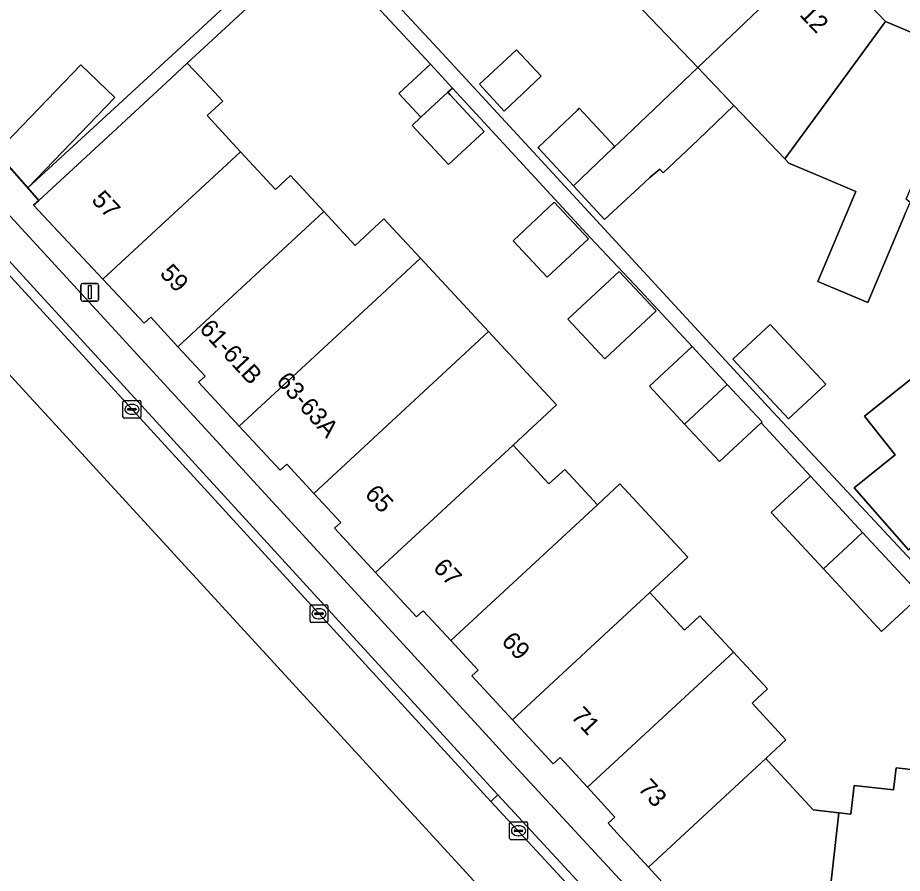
# Model space of a CAD drawing. Extents: x 160663 to 161506, y 382245 to 383291.
# Drawn here: x 160804.12 to 160853.7, y 382955.67 to 383003.62 of the extents above; entities that cross this region are included whole.
import ezdxf

# ---------------------------------------------------------------- set-up
doc = ezdxf.new("R2010")
doc.units = 0
for name, color, linetype in [('IMGEO_Berm_gesloten', 7, 'Continuous'), ('IMGEO_Berm_open', 7, 'Continuous'), ('IMGEO_Erf', 7, 'Continuous'), ('IMGEO_Fietspad_gesloten', 7, 'Continuous'), ('IMGEO_Hek', 7, 'Continuous'), ('IMGEO_Kolk', 7, 'Continuous'), ('IMGEO_Lichtmast', 7, 'Continuous'), ('IMGEO_Pand', 7, 'Continuous'), ('IMGEO_Pand_nummerreeks', 7, 'Continuous'), ('IMGEO_Rijbaan_lokaal_gesloten', 7, 'Continuous'), ('IMGEO_Voetpad_open', 7, 'Continuous')]:
    doc.layers.add(name, color=color, linetype=linetype)

msp = doc.modelspace()

# ---------------------------------------------------------------- linework, layer by layer
at = {"layer": 'IMGEO_Berm_gesloten'}
msp.add_lwpolyline([(160840.811, 382949.506), (160831.032, 382960.06), (160830.64, 382959.7), (160842.06, 382947.363), (160845.035, 382944.34)], dxfattribs=at)
at = {"layer": 'IMGEO_Berm_open'}
msp.add_lwpolyline([(160777.628, 383018.442), (160777.232, 383018.081), (160830.64, 382959.7), (160831.032, 382960.06), (160829.19, 382962.074)], close=True, dxfattribs=at)
at = {"layer": 'IMGEO_Erf'}
for points in [[(160820.979, 383009.117), (160827.916, 383001.628), (160836.559, 382992.249), (160846.446, 382981.528), (160856.563, 382970.677)], [(160803.219, 383006.978), (160797.729, 383001.848), (160802.734, 382996.483), (160803.356, 382997.063), (160803.561, 382996.843), (160802.837, 382996.169), (160802.928, 382996.067), (160802.964, 382996.104), (160807.668, 383000.985), (160809.572, 382999.15), (160804.689, 382994.083), (160813.018, 383001.742), (160820.162, 383008.359)], [(160854.741, 382971.255), (160852.536, 382969.213), (160849.276, 382972.733), (160846.36, 382975.881), (160848.565, 382977.923), (160845.786, 382980.915), (160843.448, 382978.744), (160841.495, 382980.848), (160839.527, 382982.967), (160841.924, 382985.193), (160839.009, 382988.326), (160836.207, 382991.309), (160828.491, 382999.682), (160828.231, 382999.442), (160828.361, 382999.302), (160830.27, 382997.244), (160828.268, 382995.387), (160826.227, 382997.587), (160826.726, 382998.048), (160825.491, 382999.382), (160827.256, 383001.016), (160820.93, 383007.845)], [(160820.773, 383007.699), (160813.63, 383001.082), (160814.643, 383000), (160815.625, 382998.952), (160814.739, 382998.133), (160816.611, 382996.109), (160818.57, 382993.991), (160819.413, 382994.771), (160821.274, 382992.758), (160823.029, 382990.861), (160824.645, 382992.359), (160826.701, 382990.141), (160830.511, 382986.03), (160834.318, 382981.922), (160831.885, 382979.668), (160833.899, 382977.491), (160834.78, 382978.304), (160836.612, 382976.322), (160837.878, 382977.495), (160841.69, 382973.381), (160839.553, 382971.401), (160841.496, 382969.3), (160842.359, 382970.098), (160844.239, 382968.065), (160846.148, 382966), (160845.279, 382965.197), (160847.178, 382963.143), (160846.051, 382962.099), (160846.203, 382961.935), (160848.711, 382959.223), (160850.148, 382959.057), (160850.826, 382958.978), (160851.013, 382960.595), (160853.215, 382960.341), (160853.358, 382961.58), (160856.012, 382961.273)], [(160853.869, 382992.624), (160851.769, 382987.659), (160848.972, 382988.842), (160851.103, 382993.881), (160849.256, 382994.662), (160847.348, 382995.469), (160847.11, 382995.719), (160844.266, 382998.703), (160842.253, 382996.786), (160840.301, 382994.927), (160840.106, 382995.137), (160839.566, 382994.683), (160839.211, 382994.353), (160837.02, 382992.322), (160835.278, 382994.2), (160833.332, 382996.298), (160833.286, 382996.348), (160835.493, 382998.45), (160835.601, 382998.553), (160837.594, 382996.405), (160837.793, 382996.595), (160842.238, 383000.83), (160838.295, 383004.966)]]:
    msp.add_lwpolyline(points, dxfattribs=at)
for points in [[(160831.395, 382998.386), (160829.998, 382999.892), (160832.087, 383001.83), (160833.457, 383000.353)], [(160858.301, 382972.903), (160856.2, 382975.524), (160854.056, 382973.806), (160851.005, 382977.28), (160853.31, 382979.129), (160851.584, 382981.282), (160868.693, 382994.955), (160869.499, 382993.947), (160871.428, 382995.489), (160870.623, 382996.497), (160872.873, 382998.295), (160873.684, 382997.28), (160874.675, 382985.916), (160870.465, 382991.167), (160864.317, 382986.237), (160868.471, 382981.057)], [(160833.802, 382989.08), (160831.888, 382991.119), (160834.187, 382993.277), (160836.115, 382991.224)], [(160839.899, 382987.195), (160837.034, 382984.505), (160834.955, 382986.718), (160837.838, 382989.39)], [(160849.411, 382983.079), (160847.324, 382981.141), (160844.213, 382984.491), (160846.3, 382986.429)]]:
    msp.add_lwpolyline(points, close=True, dxfattribs=at)
at = {"layer": 'IMGEO_Fietspad_gesloten'}
msp.add_lwpolyline([(160842.206, 382950.625), (160831.457, 382962.256), (160830.559, 382963.235), (160777.267, 383021.287), (160777.628, 383018.442), (160829.19, 382962.074), (160831.032, 382960.06), (160840.811, 382949.506)], dxfattribs=at)
at = {"layer": 'IMGEO_Hek'}
msp.add_lwpolyline([(160805.311, 382993.382), (160802.837, 382996.169)], dxfattribs=at)
at = {"layer": 'IMGEO_Kolk'}
for p, q in [((160810.026, 382981.246), (160810.026, 382982.098)), ((160810.101, 382982.172), (160810.953, 382982.172)), ((160811.027, 382982.098), (160811.027, 382981.246)), ((160810.285, 382981.666), (160810.285, 382981.678)), ((160810.723, 382981.629), (160810.325, 382981.629)), ((160810.328, 382981.715), (160810.726, 382981.715)), ((160810.514, 382981.952), (160810.539, 382981.952)), ((160810.769, 382981.678), (160810.769, 382981.666)), ((160810.953, 382981.172), (160810.101, 382981.172)), ((160810.537, 382981.392), (160810.512, 382981.392)), ((160820.511, 382969.791), (160820.511, 382970.643)), ((160820.586, 382970.717), (160821.438, 382970.717)), ((160821.512, 382970.643), (160821.512, 382969.791)), ((160820.77, 382970.211), (160820.77, 382970.223)), ((160821.208, 382970.174), (160820.81, 382970.174)), ((160820.813, 382970.26), (160821.211, 382970.26)), ((160820.999, 382970.497), (160821.024, 382970.497)), ((160821.254, 382970.223), (160821.254, 382970.211)), ((160821.438, 382969.717), (160820.586, 382969.717)), ((160821.022, 382969.937), (160820.997, 382969.937)), ((160831.693, 382957.624), (160831.693, 382958.476)), ((160831.768, 382958.55), (160832.62, 382958.55)), ((160832.181, 382958.33), (160832.206, 382958.33)), ((160832.694, 382958.476), (160832.694, 382957.624)), ((160831.952, 382958.044), (160831.952, 382958.056)), ((160832.39, 382958.007), (160831.992, 382958.007)), ((160831.995, 382958.093), (160832.393, 382958.093)), ((160832.204, 382957.77), (160832.179, 382957.77)), ((160832.436, 382958.056), (160832.436, 382958.044)), ((160832.62, 382957.55), (160831.768, 382957.55))]:
    msp.add_line(p, q, dxfattribs=at)
for points in [[(160810.026, 382981.246), (160810.026, 382982.098)], [(160810.101, 382982.172), (160810.953, 382982.172)], [(160811.027, 382982.098), (160811.027, 382981.246)], [(160810.953, 382981.172), (160810.101, 382981.172)], [(160820.511, 382969.791), (160820.511, 382970.643)], [(160820.586, 382970.717), (160821.438, 382970.717)], [(160821.512, 382970.643), (160821.512, 382969.791)], [(160821.438, 382969.717), (160820.586, 382969.717)], [(160831.693, 382957.624), (160831.693, 382958.476)], [(160831.768, 382958.55), (160832.62, 382958.55)], [(160832.694, 382958.476), (160832.694, 382957.624)], [(160832.62, 382957.55), (160831.768, 382957.55)]]:
    msp.add_lwpolyline(points, dxfattribs=at)
for centre, radius, start, end in [((160810.103, 382982.096), 0.0765, 91.552, 178.448), ((160810.103, 382982.096), 0.0765, 91.552, 178.448), ((160810.951, 382982.096), 0.0765, 1.552, 88.448), ((160810.951, 382982.096), 0.0765, 1.552, 88.448), ((160810.325, 382981.675), 0.0403, 85.8775, 175.7526), ((160810.322, 382981.665), 0.0366, 178.938, 274.7102), ((160810.726, 382981.672), 0.043, 264.8664, 352.4533), ((160810.73, 382981.677), 0.0386, 1.7309, 96.639), ((160810.103, 382981.248), 0.0765, 181.552, 268.448), ((160810.103, 382981.248), 0.0765, 181.552, 268.448), ((160810.951, 382981.248), 0.0765, 271.552, 358.448), ((160810.951, 382981.248), 0.0765, 271.552, 358.448), ((160820.588, 382970.641), 0.0765, 91.552, 178.448), ((160820.588, 382970.641), 0.0765, 91.552, 178.448), ((160821.436, 382970.641), 0.0765, 1.552, 88.448), ((160821.436, 382970.641), 0.0765, 1.552, 88.448), ((160820.81, 382970.22), 0.0403, 85.8775, 175.7526), ((160820.807, 382970.21), 0.0366, 178.938, 274.7102), ((160821.211, 382970.217), 0.043, 264.8664, 352.4533), ((160821.215, 382970.222), 0.0386, 1.7309, 96.639), ((160820.588, 382969.793), 0.0765, 181.552, 268.448), ((160820.588, 382969.793), 0.0765, 181.552, 268.448), ((160821.436, 382969.793), 0.0765, 271.552, 358.448), ((160821.436, 382969.793), 0.0765, 271.552, 358.448), ((160831.77, 382958.474), 0.0765, 91.552, 178.448), ((160831.77, 382958.474), 0.0765, 91.552, 178.448), ((160832.618, 382958.474), 0.0765, 1.552, 88.448), ((160832.618, 382958.474), 0.0765, 1.552, 88.448), ((160831.992, 382958.053), 0.0403, 85.8775, 175.7526), ((160831.989, 382958.043), 0.0366, 178.938, 274.7102), ((160832.393, 382958.05), 0.043, 264.8664, 352.4533), ((160832.397, 382958.055), 0.0386, 1.7309, 96.639), ((160831.77, 382957.626), 0.0765, 181.552, 268.448), ((160831.77, 382957.626), 0.0765, 181.552, 268.448), ((160832.618, 382957.626), 0.0765, 271.552, 358.448), ((160832.618, 382957.626), 0.0765, 271.552, 358.448)]:
    msp.add_arc(centre, radius, start, end, dxfattribs=at)
for centre, major_axis, ratio, start_param, end_param in [((160810.513, 382981.672), (-0.387, 0.002), 0.722429, 4.712389, 7.853982), ((160810.538, 382981.672), (-0.39, 0.002), 0.717154, 1.570796, 4.712389), ((160820.998, 382970.217), (-0.387, 0.002), 0.722429, 4.712389, 7.853982), ((160821.023, 382970.217), (-0.39, 0.002), 0.717154, 1.570796, 4.712389), ((160832.18, 382958.05), (-0.387, 0.002), 0.722429, 4.712389, 7.853982), ((160832.205, 382958.05), (-0.39, 0.002), 0.717154, 1.570796, 4.712389)]:
    msp.add_ellipse(centre, major_axis=major_axis, ratio=ratio, start_param=start_param, end_param=end_param, dxfattribs=at)
at = {"layer": 'IMGEO_Lichtmast'}
for p, q in [((160807.668, 382987.833), (160807.668, 382988.633)), ((160807.668, 382988.633), (160807.668, 382987.833)), ((160807.768, 382988.733), (160808.558, 382988.733)), ((160808.558, 382988.733), (160807.768, 382988.733)), ((160808.658, 382988.633), (160808.658, 382987.833)), ((160808.658, 382987.833), (160808.658, 382988.633)), ((160808.558, 382987.733), (160807.768, 382987.733)), ((160807.768, 382987.733), (160808.558, 382987.733))]:
    msp.add_line(p, q, dxfattribs=at)
msp.add_lwpolyline([(160808.088, 382988.608), (160808.238, 382988.608), (160808.238, 382987.858), (160808.088, 382987.858), (160808.088, 382988.608)], dxfattribs=at)
for centre, start, end in [((160807.768, 382988.633), 90, 180), ((160807.768, 382988.633), 90, 180), ((160808.558, 382988.633), 0, 90), ((160808.558, 382988.633), 360, 90), ((160807.768, 382987.833), 180, 270), ((160807.768, 382987.833), 180, 270), ((160808.558, 382987.833), 270, 0), ((160808.558, 382987.833), 270, 0)]:
    msp.add_arc(centre, 0.1, start, end, dxfattribs=at)
at = {"layer": 'IMGEO_Pand'}
for points in [[(160838.295, 383004.966), (160842.238, 383000.83), (160849.043, 383007.311), (160846.201, 383010.291), (160845.095, 383011.451)], [(160852.76, 383003.413), (160849.043, 383007.311), (160842.238, 383000.83), (160844.266, 382998.703), (160847.11, 382995.719), (160850.253, 383000)], [(160855.005, 382996.007), (160857.503, 382994.951), (160858.304, 382996.846), (160858.937, 383000), (160859.085, 383000.739), (160852.76, 383003.413), (160850.253, 383000), (160847.11, 382995.719), (160847.348, 382995.469), (160849.256, 382994.662), (160851.103, 382993.881), (160848.972, 382988.842), (160851.769, 382987.659), (160853.869, 382992.624), (160854.142, 382993.27), (160853.924, 382993.452)], [(160829.998, 382999.892), (160831.395, 382998.386), (160833.457, 383000.353), (160832.087, 383001.83)], [(160802.928, 382996.067), (160804.689, 382994.083), (160809.572, 382999.15), (160807.668, 383000.985), (160802.964, 382996.104)], [(160816.611, 382996.109), (160814.739, 382998.133), (160815.625, 382998.952), (160814.643, 383000), (160813.63, 383001.082), (160812.462, 383000), (160808.688, 382996.504), (160805.311, 382993.382), (160805.016, 382993.11), (160808.902, 382988.965)], [(160828.491, 382999.682), (160827.256, 383001.016), (160825.491, 382999.382), (160826.726, 382998.048), (160828.231, 382999.442)], [(160844.266, 382998.703), (160842.238, 383000.83), (160837.793, 382996.595), (160837.594, 382996.405), (160837.485, 382996.302), (160835.278, 382994.2), (160837.02, 382992.322), (160839.211, 382994.353), (160839.566, 382994.683), (160840.106, 382995.137), (160840.301, 382994.927), (160842.253, 382996.786)], [(160828.231, 382999.442), (160826.726, 382998.048), (160826.227, 382997.587), (160828.268, 382995.387), (160830.27, 382997.244), (160828.361, 382999.302)], [(160835.278, 382994.2), (160837.485, 382996.302), (160837.594, 382996.405), (160835.601, 382998.553), (160835.493, 382998.45), (160833.286, 382996.348), (160833.332, 382996.298)], [(160858.301, 382972.903), (160868.471, 382981.057), (160864.317, 382986.237), (160870.465, 382991.167), (160874.675, 382985.916), (160873.684, 382997.28), (160872.873, 382998.295), (160870.623, 382996.497), (160871.428, 382995.489), (160869.499, 382993.947), (160868.693, 382994.955), (160851.584, 382981.282), (160853.31, 382979.129), (160851.005, 382977.28), (160854.056, 382973.806), (160856.2, 382975.524)], [(160816.611, 382996.109), (160808.902, 382988.965), (160811.218, 382986.494), (160811.582, 382986.83), (160813.103, 382985.185), (160821.274, 382992.758), (160819.413, 382994.771), (160818.57, 382993.991)], [(160831.888, 382991.119), (160833.802, 382989.08), (160836.115, 382991.224), (160834.187, 382993.277)], [(160824.256, 382987.875), (160826.701, 382990.141), (160824.645, 382992.359), (160823.029, 382990.861), (160821.274, 382992.758), (160813.103, 382985.185), (160814.624, 382983.54), (160814.259, 382983.203), (160816.545, 382980.73)], [(160816.545, 382980.73), (160818.831, 382978.258), (160819.203, 382978.602), (160820.723, 382976.958), (160828.939, 382984.573), (160830.511, 382986.03), (160826.701, 382990.141), (160824.256, 382987.875)], [(160834.955, 382986.718), (160837.034, 382984.505), (160839.899, 382987.195), (160837.838, 382989.39)], [(160831.885, 382979.668), (160834.318, 382981.922), (160830.511, 382986.03), (160828.939, 382984.573), (160820.723, 382976.958), (160822.226, 382975.332), (160821.875, 382975.007), (160824.173, 382972.521)], [(160844.213, 382984.491), (160847.324, 382981.141), (160849.411, 382983.079), (160846.3, 382986.429)], [(160841.495, 382980.848), (160843.894, 382983.071), (160841.924, 382985.193), (160839.527, 382982.967)], [(160845.845, 382980.97), (160843.894, 382983.071), (160841.495, 382980.848), (160843.448, 382978.744), (160845.786, 382980.915)], [(160824.173, 382972.521), (160826.471, 382970.035), (160826.85, 382970.385), (160828.399, 382968.71), (160836.612, 382976.322), (160834.78, 382978.304), (160833.899, 382977.491), (160831.885, 382979.668)], [(160851.48, 382974.776), (160848.565, 382977.923), (160846.36, 382975.881), (160849.276, 382972.733)], [(160839.553, 382971.401), (160841.69, 382973.381), (160837.878, 382977.495), (160836.612, 382976.322), (160828.399, 382968.71), (160829.923, 382967.061), (160829.57, 382966.735), (160831.853, 382964.266)], [(160851.48, 382974.776), (160849.276, 382972.733), (160852.536, 382969.213), (160854.741, 382971.255)], [(160839.553, 382971.401), (160831.853, 382964.266), (160834.138, 382961.795), (160834.521, 382962.149), (160836.06, 382960.485), (160844.239, 382968.065), (160842.359, 382970.098), (160841.496, 382969.3)], [(160846.051, 382962.099), (160847.178, 382963.143), (160845.279, 382965.197), (160846.148, 382966), (160844.239, 382968.065), (160836.06, 382960.485), (160837.598, 382958.822), (160837.218, 382958.476), (160837.709, 382957.936), (160839.471, 382956.002)], [(160850.148, 382959.057), (160848.711, 382959.223), (160846.203, 382961.935), (160846.051, 382962.099), (160839.471, 382956.002), (160841.207, 382954.098), (160842.097, 382953.871), (160844.651, 382951.1), (160849.184, 382950.574)], [(160856.012, 382961.273), (160853.358, 382961.58), (160853.215, 382960.341), (160851.013, 382960.595), (160850.826, 382958.978), (160850.148, 382959.057), (160849.184, 382950.574), (160849.905, 382949.988), (160851.678, 382949.792), (160852.451, 382950.212), (160854.722, 382949.937)]]:
    msp.add_lwpolyline(points, close=True, dxfattribs=at)
at = {"layer": 'IMGEO_Rijbaan_lokaal_gesloten'}
for points in [[(160845.035, 382944.34), (160842.06, 382947.363), (160830.64, 382959.7), (160777.232, 383018.081), (160767.962, 383028.335), (160756.002, 383041.721), (160707.188, 383096.777), (160701.821, 383103.003), (160700.685, 383104.38), (160698.642, 383106.855), (160694.714, 383111.885), (160692.256, 383109.63)], [(160691.463, 383108.887), (160690.092, 383107.358), (160792.96, 382995.267), (160844.823, 382938.754), (160856.414, 382930.084)]]:
    msp.add_lwpolyline(points, dxfattribs=at)
at = {"layer": 'IMGEO_Voetpad_open'}
for points in [[(160820.723, 382976.958), (160819.203, 382978.602), (160818.831, 382978.258), (160816.545, 382980.73), (160814.259, 382983.203), (160814.624, 382983.54), (160813.103, 382985.185), (160811.582, 382986.83), (160811.218, 382986.494), (160808.902, 382988.965), (160805.016, 382993.11), (160805.311, 382993.382), (160804.689, 382994.083), (160802.928, 382996.067), (160802.837, 382996.169), (160802.719, 382996.059), (160797.509, 383001.643), (160790.688, 383008.954), (160778.405, 383022.258), (160776.924, 383023.917), (160777.267, 383021.287), (160830.559, 382963.235), (160831.457, 382962.256), (160842.206, 382950.625)], [(160846.651, 383010.726), (160846.201, 383010.291), (160849.043, 383007.311), (160852.76, 383003.413), (160859.085, 383000.739), (160864.31, 383000.334), (160868.409, 383000), (160869.446, 383000.074), (160869.436, 383000.776), (160869.225, 383001.146)], [(160856.563, 382970.677), (160846.446, 382981.528), (160836.559, 382992.249), (160827.916, 383001.628), (160820.979, 383009.117)], [(160820.162, 383008.359), (160813.018, 383001.742), (160804.689, 382994.083), (160805.311, 382993.382), (160808.688, 382996.504), (160812.462, 383000), (160813.63, 383001.082), (160820.773, 383007.699)], [(160820.93, 383007.845), (160827.256, 383001.016), (160828.491, 382999.682), (160836.207, 382991.309), (160839.009, 382988.326), (160841.924, 382985.193), (160843.894, 382983.071), (160845.845, 382980.97), (160845.786, 382980.915), (160848.565, 382977.923), (160851.48, 382974.776), (160854.741, 382971.255)], [(160847.266, 382947.954), (160844.651, 382951.1), (160842.097, 382953.871), (160841.207, 382954.098), (160839.471, 382956.002), (160837.709, 382957.936), (160837.218, 382958.476), (160837.598, 382958.822), (160836.06, 382960.485), (160834.521, 382962.149), (160834.138, 382961.795), (160831.853, 382964.266), (160829.57, 382966.735), (160829.923, 382967.061), (160828.399, 382968.71), (160826.85, 382970.385), (160826.471, 382970.035), (160824.173, 382972.521), (160821.875, 382975.007), (160822.226, 382975.332), (160820.723, 382976.958)]]:
    msp.add_lwpolyline(points, dxfattribs=at)

# ---------------------------------------------------------------- texts
at = {"layer": 'IMGEO_Pand_nummerreeks'}
for s, rotation, p in [('12', 313.642, (160847.898, 383003.759)), ('57', 312.8769, (160808.214, 382993.369)), ('59', 312.8769, (160812.043, 382989.246)), ('61-61B', 312.7596, (160814.255, 382986.149)), ('63-63A', 311.9225, (160818.567, 382983.213)), ('65', 312.8742, (160823.529, 382976.877)), ('67', 312.8769, (160827.356, 382972.753)), ('69', 312.8769, (160831.184, 382968.63)), ('71', 312.8769, (160835.09, 382964.424)), ('73', 312.8742, (160838.842, 382960.385))]:
    msp.add_text(s, height=1, rotation=rotation, dxfattribs=at).set_placement(p)

doc.saveas('drawing.dxf')
